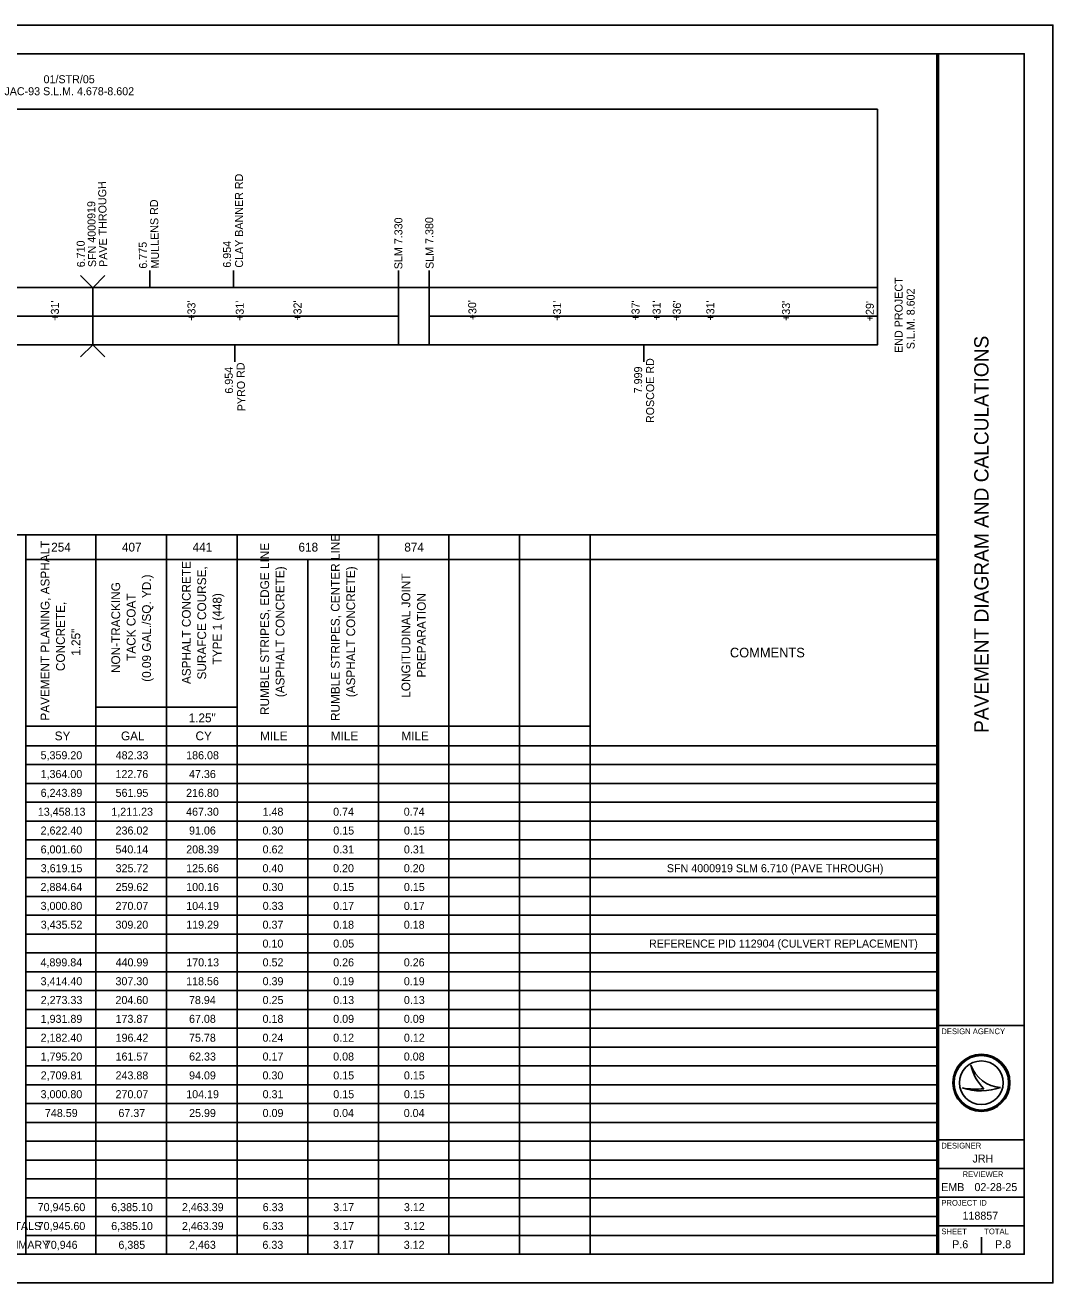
# Model space of a CAD drawing. Extents: x -16.7 to 34, y 0 to 22.
# Drawn here: x 16.03 to 34, y 0 to 22 of the extents above; entities that cross this region are included whole.
import ezdxf

# ---------------------------------------------------------------- set-up
doc = ezdxf.new("R2010")
doc.units = 0
for name, color, linetype in [('Default', 7, 'Continuous'), ('SH_Border', 7, 'Continuous'), ('SH_Cut_Line', 7, 'Continuous'), ('SH_Data', 7, 'Continuous')]:
    doc.layers.add(name, color=color, linetype=linetype)

msp = doc.modelspace()

# ---------------------------------------------------------------- linework, layer by layer
at = {"layer": 'Default'}
for p, q in [((1.5, 21.5), (31.971, 21.5)), ((31.971, 21.5), (31.971, 0.5)), ((2.511, 20.531), (30.935, 20.531)), ((30.935, 19.409), (30.935, 20.531)), ((30.935, 20.531), (30.935, 17.409)), ((16.997, 17.621), (17.209, 17.408)), ((17.209, 17.408), (17.421, 17.621)), ((18.207, 17.406), (18.207, 17.706)), ((19.673, 17.409), (19.673, 17.709)), ((22.554, 17.409), (22.554, 17.709)), ((23.094, 17.409), (23.094, 17.709)), ((2.511, 17.409), (30.935, 17.409)), ((17.209, 17.409), (17.208, 16.41)), ((30.935, 17.409), (30.935, 16.41)), ((2.511, 16.909), (22.554, 16.909)), ((23.094, 16.909), (30.935, 16.909)), ((30.935, 16.41), (2.511, 16.41)), ((16.996, 16.197), (17.208, 16.41)), ((17.208, 16.41), (17.421, 16.197)), ((19.693, 16.409), (19.693, 16.109)), ((26.846, 16.408), (26.846, 16.108)), ((13.891, 13.084), (16.038, 13.084)), ((16.016, 13.084), (31.971, 13.084)), ((16.038, 13.084), (16.038, 0.5)), ((17.262, 13.084), (17.262, 0.5)), ((18.498, 13.084), (18.498, 0.5)), ((19.733, 13.084), (19.733, 0.5)), ((22.204, 13.084), (22.204, 0.5)), ((23.439, 13.084), (23.439, 0.5)), ((24.674, 13.084), (24.674, 0.5)), ((25.909, 13.084), (25.909, 0.5)), ((16.038, 12.655), (31.971, 12.655)), ((20.968, 12.655), (20.968, 0.5)), ((17.262, 10.069), (19.733, 10.069)), ((16.038, 9.74), (25.909, 9.74)), ((16.038, 9.394), (31.971, 9.394)), ((16.038, 9.065), (31.971, 9.065)), ((16.038, 8.735), (31.971, 8.735)), ((16.038, 8.406), (31.971, 8.406)), ((16.038, 8.076), (31.971, 8.076)), ((16.038, 7.747), (31.971, 7.747)), ((16.038, 7.418), (31.971, 7.418)), ((16.038, 7.088), (31.971, 7.088)), ((16.038, 6.759), (31.971, 6.759)), ((16.038, 6.429), (31.971, 6.429)), ((16.038, 6.1), (31.971, 6.1)), ((16.038, 5.771), (31.971, 5.771)), ((16.038, 5.441), (31.971, 5.441)), ((16.038, 5.112), (31.971, 5.112)), ((16.038, 4.782), (31.971, 4.782)), ((16.038, 4.453), (31.971, 4.453)), ((16.038, 4.124), (31.971, 4.124)), ((16.038, 3.794), (31.971, 3.794)), ((16.038, 3.465), (31.971, 3.465)), ((16.038, 3.135), (31.971, 3.135)), ((16.038, 2.806), (31.971, 2.806)), ((16.038, 2.476), (31.971, 2.476)), ((16.038, 2.147), (31.971, 2.147)), ((16.038, 1.818), (31.971, 1.818)), ((16.038, 1.488), (31.971, 1.488)), ((16.038, 1.159), (31.971, 1.159)), ((16.038, 0.829), (31.971, 0.829)), ((1.5, 0.5), (16.038, 0.5)), ((16.016, 0.5), (31.971, 0.5))]:
    msp.add_line(p, q, dxfattribs=at)
for points in [[(22.554, 16.41), (2.511, 16.41), (2.511, 17.409), (17.208, 17.409), (17.209, 17.408), (17.209, 17.409), (22.554, 17.409)], [(23.094, 17.409), (30.935, 17.41), (30.935, 16.41), (23.094, 16.409)]]:
    msp.add_lwpolyline(points, close=True, dxfattribs=at)
at = {"layer": 'SH_Border'}
for p, q in [((32, 0.5), (32, 21.5)), ((32, 4.5), (33.5, 4.5)), ((32, 2.5), (33.5, 2.5)), ((32, 2), (33.5, 2)), ((32, 1.5), (33.5, 1.5)), ((32, 1), (33.5, 1))]:
    msp.add_line(p, q, dxfattribs=at)
msp.add_lwpolyline([(1.5, 21.5), (33.5, 21.5), (33.5, 0.5), (1.5, 0.5)], close=True, dxfattribs=at)
at = {"layer": 'SH_Cut_Line'}
msp.add_lwpolyline([(0, 0), (34, 0), (34, 22), (0, 22)], close=True, dxfattribs=at)
at = {"layer": 'SH_Data'}
for p, q in [((32.567, 3.81), (32.567, 3.81)), ((32.417, 3.41), (32.417, 3.41)), ((32.75, 3.5), (32.75, 3.5)), ((33.087, 3.419), (33.087, 3.419)), ((32.375, 0.675), (32.375, 0.675)), ((32.75, 0.5), (32.75, 0.8))]:
    msp.add_line(p, q, dxfattribs=at)
for radius in [0.5, 0.477, 0.477, 0.382]:
    msp.add_circle((32.75, 3.5), radius, dxfattribs=at)
for centre, radius, start, end in [((33.116, 3.998), 0.58, 198.9257, 198.9319), ((33.347, 3.97), 0.796, 191.6379, 191.6421), ((33.116, 3.998), 0.58, 198.9319, 267.1657), ((33.347, 3.97), 0.796, 191.6421, 226.0947), ((32.739, 4.37), 1.013, 251.4576, 290.0832), ((32.648, 4.654), 1.266, 259.4964, 259.4995), ((32.739, 4.37), 1.013, 251.4527, 251.4576), ((32.648, 4.654), 1.266, 259.4995, 276.6672)]:
    msp.add_arc(centre, radius, start, end, dxfattribs=at)

# ---------------------------------------------------------------- texts
at = {"layer": 'Default'}
for s, height, p in [('01/STR/05', 0.14, (16.349, 20.984)), ('JAC-93 S.L.M. 4.678-8.602', 0.14, (15.664, 20.774)), ('254', 0.154, (16.482, 12.792)), ('407', 0.154, (17.719, 12.792)), ('441', 0.154, (18.955, 12.792)), ('618', 0.154, (20.807, 12.792)), ('874', 0.154, (22.658, 12.792)), ('COMMENTS', 0.168, (28.352, 10.941)), ('1.25"', 0.154, (18.886, 9.806)), ('SY', 0.154, (16.544, 9.49)), ('GAL', 0.154, (17.703, 9.49)), ('CY', 0.154, (19.006, 9.49)), ('MILE', 0.154, (20.136, 9.49)), ('MILE', 0.154, (21.372, 9.49)), ('MILE', 0.154, (22.607, 9.49)), ('5,359.20', 0.14, (16.297, 9.159)), ('482.33', 0.14, (17.61, 9.159)), ('186.08', 0.14, (18.843, 9.159)), ('1,364.00', 0.14, (16.297, 8.83)), ('122.76', 0.14, (17.607, 8.83)), ('47.36', 0.14, (18.893, 8.83)), ('6,243.89', 0.14, (16.298, 8.501)), ('561.95', 0.14, (17.609, 8.501)), ('216.80', 0.14, (18.842, 8.501)), ('13,458.13', 0.14, (16.249, 8.171)), ('1,211.23', 0.14, (17.534, 8.171)), ('467.30', 0.14, (18.842, 8.171)), ('1.48', 0.14, (20.179, 8.171)), ('0.74', 0.14, (21.413, 8.171)), ('0.74', 0.14, (22.648, 8.171)), ('2,622.40', 0.14, (16.297, 7.842)), ('236.02', 0.14, (17.609, 7.842)), ('91.06', 0.14, (18.893, 7.842)), ('0.30', 0.14, (20.178, 7.842)), ('0.15', 0.14, (21.416, 7.842)), ('0.15', 0.14, (22.651, 7.842)), ('6,001.60', 0.14, (16.297, 7.512)), ('540.14', 0.14, (17.606, 7.512)), ('208.39', 0.14, (18.844, 7.512)), ('0.62', 0.14, (20.18, 7.512)), ('0.31', 0.14, (21.415, 7.512)), ('0.31', 0.14, (22.651, 7.512)), ('3,619.15', 0.14, (16.299, 7.183)), ('325.72', 0.14, (17.609, 7.183)), ('125.66', 0.14, (18.843, 7.183)), ('0.40', 0.14, (20.178, 7.183)), ('0.20', 0.14, (21.413, 7.183)), ('0.20', 0.14, (22.649, 7.183)), ('SFN 4000919 SLM 6.710 (PAVE THROUGH)', 0.14, (27.25, 7.183)), ('2,884.64', 0.14, (16.296, 6.854)), ('259.62', 0.14, (17.609, 6.854)), ('100.16', 0.14, (18.843, 6.854)), ('0.30', 0.14, (20.178, 6.854)), ('0.15', 0.14, (21.416, 6.854)), ('0.15', 0.14, (22.651, 6.854)), ('3,000.80', 0.14, (16.297, 6.524)), ('270.07', 0.14, (17.608, 6.524)), ('104.19', 0.14, (18.844, 6.524)), ('0.33', 0.14, (20.181, 6.524)), ('0.17', 0.14, (21.415, 6.524)), ('0.17', 0.14, (22.65, 6.524)), ('3,435.52', 0.14, (16.299, 6.195)), ('309.20', 0.14, (17.607, 6.195)), ('119.29', 0.14, (18.844, 6.195)), ('0.37', 0.14, (20.179, 6.195)), ('0.18', 0.14, (21.414, 6.195)), ('0.18', 0.14, (22.649, 6.195)), ('0.10', 0.14, (20.178, 5.865)), ('0.05', 0.14, (21.416, 5.865)), ('REFERENCE PID 112904 (CULVERT REPLACEMENT)', 0.14, (26.937, 5.865)), ('4,899.84', 0.14, (16.296, 5.536)), ('440.99', 0.14, (17.609, 5.536)), ('170.13', 0.14, (18.845, 5.536)), ('0.52', 0.14, (20.18, 5.536)), ('0.26', 0.14, (21.414, 5.536)), ('0.26', 0.14, (22.649, 5.536)), ('3,414.40', 0.14, (16.297, 5.206)), ('307.30', 0.14, (17.607, 5.206)), ('118.56', 0.14, (18.843, 5.206)), ('0.39', 0.14, (20.18, 5.206)), ('0.19', 0.14, (21.415, 5.206)), ('0.19', 0.14, (22.65, 5.206)), ('2,273.33', 0.14, (16.299, 4.877)), ('204.60', 0.14, (17.607, 4.877)), ('78.94', 0.14, (18.892, 4.877)), ('0.25', 0.14, (20.18, 4.877)), ('0.13', 0.14, (21.416, 4.877)), ('0.13', 0.14, (22.651, 4.877)), ('1,931.89', 0.14, (16.298, 4.548)), ('173.87', 0.14, (17.608, 4.548)), ('67.08', 0.14, (18.893, 4.548)), ('0.18', 0.14, (20.179, 4.548)), ('0.09', 0.14, (21.415, 4.548)), ('0.09', 0.14, (22.65, 4.548)), ('2,182.40', 0.14, (16.297, 4.218)), ('196.42', 0.14, (17.609, 4.218)), ('75.78', 0.14, (18.893, 4.218)), ('0.24', 0.14, (20.178, 4.218)), ('0.12', 0.14, (21.415, 4.218)), ('0.12', 0.14, (22.651, 4.218)), ('1,795.20', 0.14, (16.297, 3.889)), ('161.57', 0.14, (17.608, 3.889)), ('62.33', 0.14, (18.895, 3.889)), ('0.17', 0.14, (20.179, 3.889)), ('0.08', 0.14, (21.414, 3.889)), ('0.08', 0.14, (22.649, 3.889)), ('2,709.81', 0.14, (16.299, 3.559)), ('243.88', 0.14, (17.608, 3.559)), ('94.09', 0.14, (18.894, 3.559)), ('0.30', 0.14, (20.178, 3.559)), ('0.15', 0.14, (21.416, 3.559)), ('0.15', 0.14, (22.651, 3.559)), ('3,000.80', 0.14, (16.297, 3.23)), ('270.07', 0.14, (17.608, 3.23)), ('104.19', 0.14, (18.844, 3.23)), ('0.31', 0.14, (20.18, 3.23)), ('0.15', 0.14, (21.416, 3.23)), ('0.15', 0.14, (22.651, 3.23)), ('748.59', 0.14, (16.373, 2.901)), ('67.37', 0.14, (17.658, 2.901)), ('25.99', 0.14, (18.894, 2.901)), ('0.09', 0.14, (20.18, 2.901)), ('0.04', 0.14, (21.413, 2.901)), ('0.04', 0.14, (22.648, 2.901)), ('70,945.60', 0.14, (16.246, 1.254)), ('6,385.10', 0.14, (17.532, 1.254)), ('2,463.39', 0.14, (18.769, 1.254)), ('6.33', 0.14, (20.181, 1.254)), ('3.17', 0.14, (21.415, 1.254)), ('3.12', 0.14, (22.651, 1.254)), ('THIS SHEET TOTALS', 0.14, (14.424, 0.924)), ('70,945.60', 0.14, (16.246, 0.924)), ('6,385.10', 0.14, (17.532, 0.924)), ('2,463.39', 0.14, (18.769, 0.924)), ('6.33', 0.14, (20.181, 0.924)), ('3.17', 0.14, (21.415, 0.924)), ('3.12', 0.14, (22.651, 0.924)), ('TOTALS CARRIED TO GENERAL SUMMARY', 0.14, (12.559, 0.595)), ('70,946', 0.14, (16.371, 0.595)), ('6,385', 0.14, (17.658, 0.595)), ('2,463', 0.14, (18.893, 0.595)), ('6.33', 0.14, (20.177, 0.595)), ('3.17', 0.14, (21.413, 0.595)), ('3.12', 0.14, (22.648, 0.595))]:
    msp.add_text(s, height=height, dxfattribs=at).set_placement(p)
for s, height, rotation, p in [('CLAY BANNER RD', 0.14, 90.0485, (19.838, 17.758)), ('PAVE THROUGH', 0.14, 90.8418, (17.464, 17.772)), ('MULLENS RD', 0.14, 91.0692, (18.371, 17.746)), ('SFN 4000919', 0.14, 90.8418, (17.269, 17.769)), ('SLM 7.330', 0.14, 89.9304, (22.624, 17.731)), ('SLM 7.380', 0.14, 90.5204, (23.171, 17.737)), ('6.710', 0.14, 90.8418, (17.074, 17.766)), ('6.775', 0.14, 91.0692, (18.161, 17.742)), ('6.954', 0.14, 90.0485, (19.628, 17.758)), ('END PROJECT', 0.14, 90, (31.373, 16.267)), ('S.L.M. 8.602', 0.14, 90, (31.583, 16.332)), ("+31'", 0.14, 90, (16.617, 16.83)), ("+33'", 0.14, 90, (19.005, 16.829)), ("+31'", 0.14, 90, (19.85, 16.827)), ("+32'", 0.14, 90, (20.86, 16.831)), ("+30'", 0.14, 92.7391, (23.927, 16.841)), ("+31'", 0.14, 90, (25.399, 16.828)), ("+37'", 0.14, 90, (26.772, 16.831)), ("+31'", 0.14, 90, (27.14, 16.831)), ("+36'", 0.14, 88.0267, (27.486, 16.826)), ("+31'", 0.14, 90, (28.08, 16.832)), ("+33'", 0.14, 90, (29.404, 16.825)), ("+29'", 0.14, 89.5099, (30.867, 16.82)), ('PYRO RD', 0.14, 91.2482, (19.881, 15.248)), ('ROSCOE RD', 0.14, 90.0068, (27.027, 15.04)), ('      6.954', 0.14, 91.2482, (19.671, 15.244)), ('          7.999', 0.14, 90.0068, (26.817, 15.04)), ('RUMBLE STRIPES, CENTER LINE ', 0.154, 90, (21.528, 9.828)), ('PAVEMENT PLANING, ASPHALT ', 0.154, 90, (16.452, 9.835)), ('RUMBLE STRIPES, EDGE LINE ', 0.154, 90, (20.293, 9.933)), ('ASPHALT CONCRETE ', 0.154, 90, (18.923, 10.474)), ('(0.09 GAL./SQ. YD.)', 0.154, 90, (18.227, 10.514)), ('SURAFCE COURSE, ', 0.154, 90, (19.192, 10.554)), ('(ASPHALT CONCRETE)', 0.154, 90, (20.562, 10.244)), ('(ASPHALT CONCRETE)', 0.154, 90, (21.798, 10.244)), ('LONGITUDINAL JOINT ', 0.154, 90, (22.763, 10.235)), ('NON-TRACKING ', 0.154, 90, (17.688, 10.667)), ('CONCRETE, ', 0.154, 90, (16.722, 10.701)), ('TACK COAT', 0.154, 90, (17.957, 10.88)), ('TYPE 1 (448)', 0.154, 90, (19.462, 10.817)), ('PREPARATION', 0.154, 90, (23.033, 10.589)), ('1.25"', 0.154, 90, (16.991, 10.969))]:
    msp.add_text(s, height=height, rotation=rotation, dxfattribs=at).set_placement(p)
at = {"layer": 'SH_Data'}
msp.add_text('PAVEMENT DIAGRAM AND CALCULATIONS', height=0.25, rotation=90, dxfattribs=at).set_placement((32.875, 9.62))
for s, height, p in [('DESIGN AGENCY', 0.1, (32.05, 4.35)), ('DESIGNER', 0.1, (32.05, 2.35)), ('JRH', 0.14, (32.595, 2.105)), ('REVIEWER', 0.1, (32.422, 1.85)), ('EMB', 0.14, (32.047, 1.605)), ('02-28-25', 0.14, (32.629, 1.605)), ('PROJECT ID', 0.1, (32.05, 1.35)), ('118857', 0.14, (32.42, 1.105)), ('SHEET', 0.1, (32.05, 0.85)), ('TOTAL', 0.1, (32.8, 0.85)), ('P.6', 0.14, (32.239, 0.605)), ('P.8', 0.14, (32.989, 0.605))]:
    msp.add_text(s, height=height, dxfattribs=at).set_placement(p)

doc.saveas('drawing.dxf')
